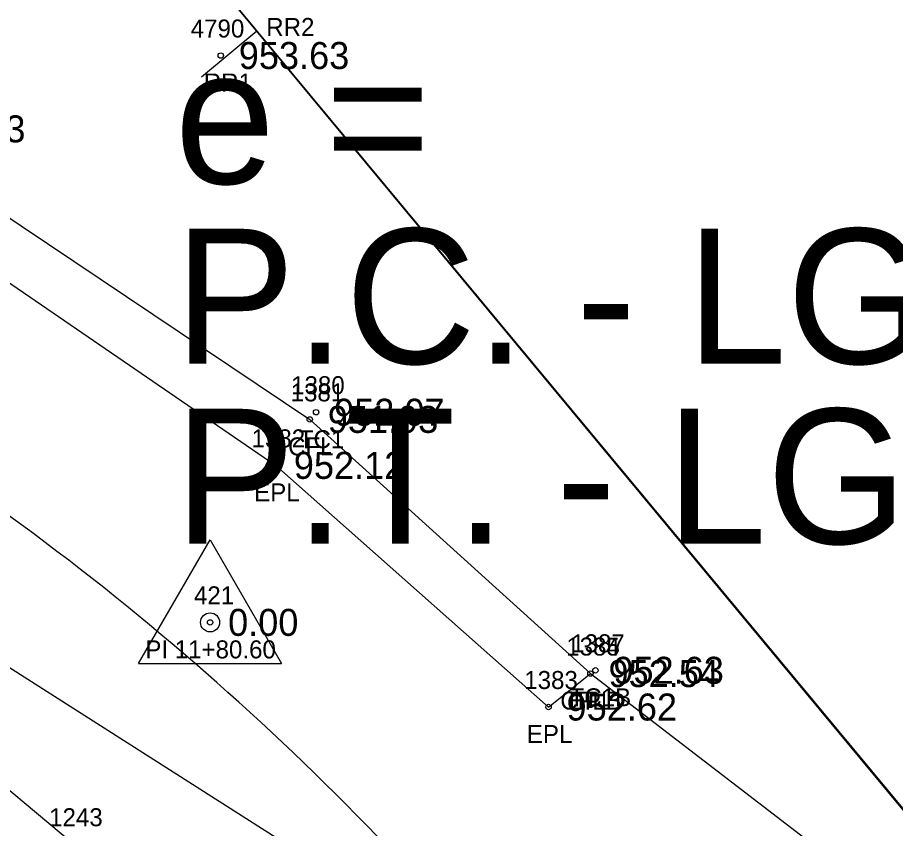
# Model space of a CAD drawing. Extents: x 1575382 to 1578175, y 1099175 to 1101955.
# Drawn here: x 1576354.28 to 1576403.03, y 1099648.19 to 1099693.23 of the extents above; entities that cross this region are included whole.
import ezdxf

# ---------------------------------------------------------------- set-up
doc = ezdxf.new("R2010")
doc.units = 0
for name, color, linetype in [('RD_EX_Conc', 7, 'Continuous'), ('RD_EX_Conc_txCode', 7, 'Continuous'), ('RD_EX_RailRoad', 7, 'Continuous'), ('RD_EX_RailRoad_txCode', 7, 'Continuous'), ('RD_EX_Road', 7, 'Continuous'), ('RD_EX_Road_txCode', 7, 'Continuous'), ('RD_EX_TX_Conc_ELEV', 7, 'Continuous'), ('RD_EX_TX_RailRoad_ELEV', 7, 'Continuous'), ('RD_EX_TX_Road_ELEV', 7, 'Continuous'), ('RD_EX_UT', 7, 'Continuous'), ('RD_HC_Cl', 7, 'Continuous'), ('RD_HC_Data', 7, 'Continuous'), ('RD_HC_Data_Tic', 7, 'Continuous'), ('RD_HC_Survey_ELEV', 7, 'Continuous'), ('RD_HC_txCode', 7, 'Continuous'), ('RD_SMD_Locator', 7, 'Continuous')]:
    doc.layers.add(name, color=color, linetype=linetype)

msp = doc.modelspace()

# ---------------------------------------------------------------- linework, layer by layer
at = {"layer": 'RD_EX_Conc'}
msp.add_lwpolyline([(1576289.772, 1099728.043), (1576287.797, 1099722.95), (1576303.934, 1099713.359), (1576347.204, 1099686.538), (1576370.503, 1099670.912), (1576386.093, 1099656.794)], dxfattribs=at)
at = {"layer": 'RD_EX_RailRoad'}
msp.add_lwpolyline([(1576586.778, 1099428.105), (1576554.904, 1099466.707), (1576523.695, 1099504.276), (1576490.272, 1099544.766), (1576459.306, 1099582.088), (1576445.84, 1099598.336), (1576409.987, 1099641.437), (1576367.438, 1099692.664), (1576334.672, 1099732.084), (1576298.682, 1099775.456), (1576256.762, 1099825.945)], dxfattribs=at)
at = {"layer": 'RD_EX_Road'}
for points in [[(1576217.778, 1099763.81), (1576263.481, 1099736.456), (1576283.453, 1099724.575), (1576282.377, 1099722.879), (1576302.495, 1099710.797), (1576345.462, 1099684.213), (1576368.618, 1099668.357), (1576383.763, 1099654.936), (1576386.093, 1099656.794), (1576408.063, 1099639.915), (1576408.063, 1099639.915), (1576411.911, 1099642.96), (1576420.57, 1099654.577), (1576428.781, 1099665.98), (1576435.656, 1099661.474), (1576436.12, 1099661.139), (1576438.458, 1099659.425), (1576459.371, 1099692.406), (1576486.603, 1099735.591), (1576512.848, 1099776.73), (1576539.458, 1099818.98), (1576543.778, 1099825.474), (1576541.419, 1099827.154), (1576542.918, 1099831.854)], [(1576385.974, 1099603.197), (1576388.618, 1099605.879), (1576388.149, 1099611.282), (1576384.699, 1099615.456), (1576386.165, 1099616.781), (1576370.202, 1099635.027), (1576357.376, 1099647.313), (1576346.631, 1099656.319), (1576334.076, 1099664.489), (1576324.149, 1099670.375), (1576289.725, 1099690.815), (1576247.005, 1099716.046), (1576203.005, 1099742.272)]]:
    msp.add_lwpolyline(points, dxfattribs=at)
at = {"layer": 'RD_EX_UT'}
msp.add_lwpolyline([(1576131.494, 1099798.742), (1576305.274, 1099688.085), (1576417.784, 1099616.336), (1576572.134, 1099536.517)], dxfattribs=at)
at = {"layer": 'RD_HC_Cl'}
msp.add_line((1576594.9, 1099418.511), (1576256.801, 1099825.977), dxfattribs=at)
msp.add_arc((1576263.295, 1099540.963), 154, 39.62889, 59.19519, dxfattribs=at)
at = {"layer": 'RD_HC_Data'}
for p, q in [((1576360.998, 1099657.345), (1576364.97, 1099664.224)), ((1576364.97, 1099664.224), (1576368.938, 1099657.345)), ((1576360.998, 1099657.345), (1576368.938, 1099657.345))]:
    msp.add_line(p, q, dxfattribs=at)
msp.add_circle((1576364.968, 1099659.637), 0.529, dxfattribs=at)
at = {"layer": 'RD_HC_Data_Tic'}
msp.add_line((1576367.572, 1099692.479), (1576364.494, 1099689.925), dxfattribs=at)
at = {"layer": 'RD_SMD_Locator'}
for centre in [(1576365.561, 1099691.122), (1576370.855, 1099671.31), (1576370.503, 1099670.912), (1576368.618, 1099668.357), (1576364.968, 1099659.637), (1576386.366, 1099656.975), (1576386.093, 1099656.794), (1576386.093, 1099656.794), (1576383.763, 1099654.936)]:
    msp.add_circle(centre, 0.15, dxfattribs=at)

# ---------------------------------------------------------------- texts
at = {"layer": 'RD_EX_Conc_txCode'}
for s, p in [('1380', (1576369.469, 1099672.31)), ('1381', (1576369.44, 1099671.912)), ('TC1', (1576369.894, 1099669.31)), ('CFL', (1576369.298, 1099668.912)), ('1384', (1576384.746, 1099657.794)), ('1387', (1576385.019, 1099657.975)), ('CFLB', (1576384.416, 1099654.794)), ('TC1B', (1576384.933, 1099654.975))]:
    msp.add_text(s, height=1, dxfattribs=at).set_placement(p)
at = {"layer": 'RD_EX_RailRoad_txCode'}
for s, p in [('4790', (1576363.892, 1099692.122)), ('RR2', (1576368.086, 1099692.207)), ('RR1', (1576364.616, 1099689.122))]:
    msp.add_text(s, height=1, dxfattribs=at).set_placement(p)
at = {"layer": 'RD_EX_Road_txCode'}
for s, p in [('1382', (1576367.272, 1099669.357)), ('EPL', (1576367.414, 1099666.357)), ('1385', (1576384.746, 1099657.794)), ('1383', (1576382.416, 1099655.936)), ('EPL', (1576384.888, 1099654.794)), ('EPL', (1576382.558, 1099652.936)), ('1243', (1576356.029, 1099648.313))]:
    msp.add_text(s, height=1, dxfattribs=at).set_placement(p)
at = {"layer": 'RD_EX_TX_Conc_ELEV'}
for s, p in [('951.63', (1576348.578, 1099686.297)), ('952.07', (1576371.855, 1099670.56)), ('951.93', (1576371.503, 1099670.162)), ('952.54', (1576387.093, 1099656.044)), ('952.63', (1576387.366, 1099656.225))]:
    msp.add_text(s, height=1.5, dxfattribs=at).set_placement(p)
at = {"layer": 'RD_EX_TX_RailRoad_ELEV'}
msp.add_text('953.63', height=1.5, dxfattribs=at).set_placement((1576366.561, 1099690.372))
at = {"layer": 'RD_EX_TX_Road_ELEV'}
for s, p in [('952.12', (1576369.618, 1099667.607)), ('952.54', (1576387.093, 1099656.044)), ('952.62', (1576384.763, 1099654.186))]:
    msp.add_text(s, height=1.5, dxfattribs=at).set_placement(p)
at = {"layer": 'RD_HC_Data'}
for s, p in [('e = ', (1576363, 1099684)), ('P.C. - LG% = ', (1576363, 1099674)), ('P.T. - LG% = ', (1576363, 1099664))]:
    msp.add_text(s, height=7.5, dxfattribs=at).set_placement(p)
at = {"layer": 'RD_HC_Survey_ELEV'}
msp.add_text('0.00', height=1.5, dxfattribs=at).set_placement((1576365.968, 1099658.887))
at = {"layer": 'RD_HC_txCode'}
for s, p in [('421', (1576364.071, 1099660.637)), ('PI 11+80.60', (1576361.37, 1099657.637))]:
    msp.add_text(s, height=1, dxfattribs=at).set_placement(p)

doc.saveas('drawing.dxf')
